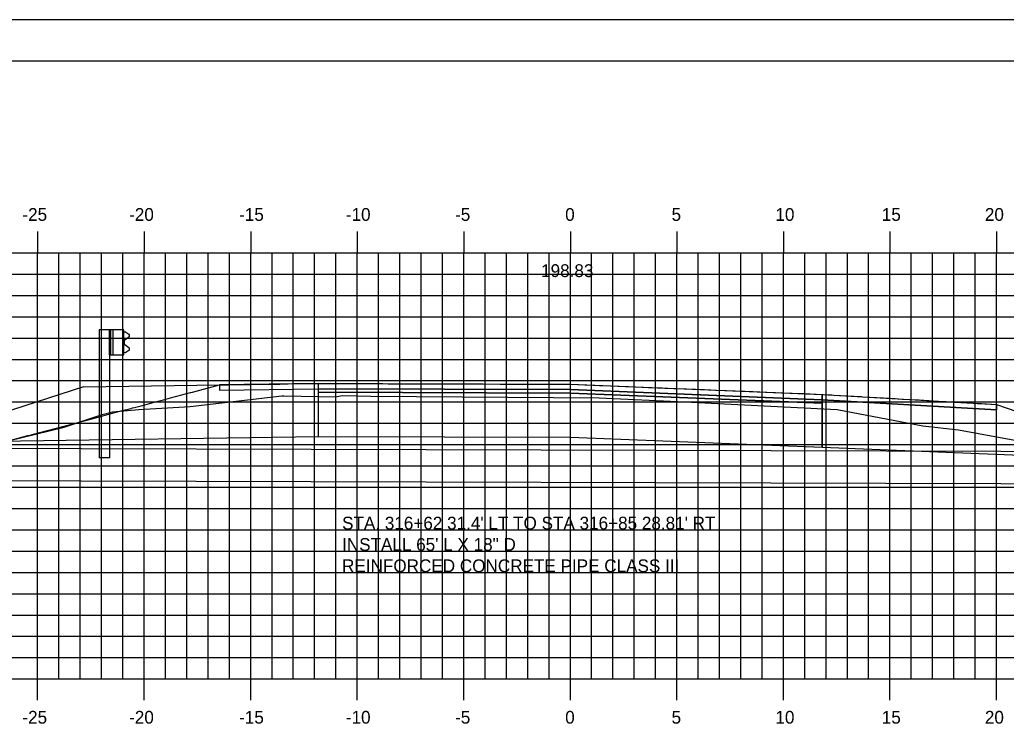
# Model space of a CAD drawing. Extents: x 1138763 to 1138933, y 608981 to 609091.
# Drawn here: x 1138820.35 to 1138866.65, y 609057.92 to 609091.28 of the extents above; entities that cross this region are included whole.
import ezdxf

# ---------------------------------------------------------------- set-up
doc = ezdxf.new("R2010")
doc.units = 0
for name, color, linetype in [('ANNOTATION', 7, 'Continuous'), ('BORDER', 7, 'Continuous'), ('D_Drainage_Culvert', 7, 'Continuous'), ('D_Guardrail_Beam_Lt', 7, 'Continuous'), ('D_Roadway_Centerline', 7, 'Continuous'), ('D_Roadway_Centerline_Text', 7, 'Continuous'), ('D_Roadway_Edge_Shoulder', 7, 'Continuous'), ('D_Roadway_Edge_TW', 7, 'Continuous'), ('D_Roadway_Pavement', 7, 'Continuous'), ('D_Roadway_SubGrade', 7, 'Continuous'), ('H_V ANNOTATION', 7, 'Continuous'), ('MAJOR', 7, 'Continuous'), ('MINOR', 7, 'Continuous'), ('PLOT BOUNDARY', 7, 'Continuous'), ('S_Roadway_Centerline', 7, 'Continuous')]:
    doc.layers.add(name, color=color, linetype=linetype)

msp = doc.modelspace()

# ---------------------------------------------------------------- linework, layer by layer
msp.add_lwpolyline([(1138819.656, 609071.467), (1138820.738, 609071.753), (1138820.904, 609071.797), (1138820.939, 609071.806), (1138822.441, 609072.204), (1138822.794, 609072.298), (1138823.978, 609072.611), (1138824.65, 609072.789), (1138825.12, 609072.913), (1138825.57, 609073.032), (1138825.644, 609073.052), (1138825.734, 609073.076), (1138826.049, 609073.159), (1138826.506, 609073.28), (1138826.704, 609073.333), (1138827.098, 609073.437), (1138827.421, 609073.523), (1138828.362, 609073.772), (1138828.377, 609073.776), (1138828.461, 609073.798), (1138828.628, 609073.842), (1138829.729, 609074.134), (1138829.729, 609074.134), (1138829.73, 609074.134), (1138829.805, 609074.135), (1138829.825, 609074.135), (1138830.183, 609074.141), (1138830.218, 609074.141), (1138830.953, 609074.152), (1138831.189, 609074.156), (1138831.718, 609074.164), (1138832.074, 609074.169), (1138832.299, 609074.173), (1138832.553, 609074.177), (1138832.949, 609074.183), (1138833.753, 609074.195), (1138833.899, 609074.197), (1138833.917, 609074.197), (1138833.929, 609074.198), (1138833.93, 609074.198), (1138834.369, 609074.204), (1138835.187, 609074.202), (1138835.281, 609074.201), (1138835.728, 609074.2), (1138835.786, 609074.2), (1138835.875, 609074.199), (1138836.481, 609074.197), (1138836.511, 609074.197), (1138836.645, 609074.197), (1138837.387, 609074.194), (1138837.642, 609074.193), (1138837.747, 609074.193), (1138838.009, 609074.192), (1138838.855, 609074.189), (1138839.373, 609074.188), (1138839.426, 609074.188), (1138839.498, 609074.187), (1138840.098, 609074.185), (1138840.737, 609074.183), (1138841.007, 609074.182), (1138841.354, 609074.181), (1138841.825, 609074.18), (1138842.1, 609074.179), (1138842.901, 609074.176), (1138843.21, 609074.175), (1138843.273, 609074.175), (1138843.464, 609074.175), (1138844.65, 609074.171), (1138844.828, 609074.17), (1138844.855, 609074.17), (1138845.066, 609074.17), (1138846.192, 609074.166), (1138846.879, 609074.139), (1138846.922, 609074.137), (1138846.963, 609074.135), (1138847.556, 609074.111), (1138847.713, 609074.105), (1138848.778, 609074.062), (1138848.809, 609074.061), (1138848.92, 609074.057), (1138849.861, 609074.019), (1138850.284, 609074.002), (1138850.506, 609073.993), (1138850.634, 609073.988), (1138851.05, 609073.971), (1138851.648, 609073.947), (1138852.066, 609073.93), (1138852.489, 609073.913), (1138852.78, 609073.902), (1138853.012, 609073.892), (1138853.519, 609073.872), (1138854.345, 609073.839), (1138854.355, 609073.839), (1138854.376, 609073.838), (1138854.752, 609073.823), (1138855.739, 609073.783), (1138855.825, 609073.78), (1138856.201, 609073.765), (1138857.028, 609073.732), (1138857.103, 609073.729), (1138857.171, 609073.726), (1138858.015, 609073.692), (1138858.057, 609073.69), (1138858.059, 609073.69), (1138858.467, 609073.666), (1138858.554, 609073.661), (1138859.831, 609073.586), (1138859.849, 609073.585), (1138859.913, 609073.581), (1138860.255, 609073.561), (1138861.195, 609073.506), (1138861.429, 609073.493), (1138861.769, 609073.473), (1138862.162, 609073.45), (1138862.559, 609073.427), (1138863.229, 609073.388), (1138863.625, 609073.364), (1138863.834, 609073.352), (1138863.923, 609073.347), (1138865.098, 609073.279), (1138865.287, 609073.268), (1138865.463, 609073.257), (1138865.481, 609073.256), (1138866.197, 609073.214), (1138866.651, 609073.059)])
at = {"layer": 'BORDER'}
msp.add_lwpolyline([(1138771.192, 608984.335), (1138931.192, 608984.335), (1138931.192, 609089.335), (1138771.192, 609089.335)], close=True, dxfattribs=at)
at = {"layer": 'D_Drainage_Culvert'}
msp.add_lwpolyline([(1138812.433, 609069.671), (1138877.192, 609069.481), (1138877.196, 609070.981), (1138812.438, 609071.171)], close=True, dxfattribs=at)
at = {"layer": 'D_Guardrail_Beam_Lt'}
for p, q in [((1138824.083, 609076.717), (1138824.083, 609070.717)), ((1138824.554, 609076.717), (1138824.083, 609076.717)), ((1138825.241, 609076.717), (1138824.554, 609076.717)), ((1138824.554, 609076.717), (1138824.554, 609075.551)), ((1138824.616, 609076.717), (1138824.616, 609075.551)), ((1138824.72, 609076.717), (1138824.72, 609075.551)), ((1138825.241, 609075.551), (1138825.241, 609076.717)), ((1138825.241, 609076.634), (1138825.315, 609076.619)), ((1138825.331, 609076.613), (1138825.475, 609076.513)), ((1138825.246, 609076.169), (1138825.246, 609076.099)), ((1138825.475, 609076.37), (1138825.279, 609076.234)), ((1138825.279, 609076.035), (1138825.475, 609075.898)), ((1138825.315, 609075.649), (1138825.241, 609075.634)), ((1138825.475, 609075.755), (1138825.331, 609075.655)), ((1138824.554, 609075.551), (1138825.241, 609075.551)), ((1138824.575, 609070.717), (1138824.575, 609075.551)), ((1138824.575, 609070.717), (1138824.083, 609070.717))]:
    msp.add_line(p, q, dxfattribs=at)
for centre, major_axis, start_param, end_param in [((1138825.307, 609076.579), (0.0417, 0), 0.959931, 1.376053), ((1138825.424, 609076.441), (0.0877, 0), 5.323254, 7.243116), ((1138825.325, 609076.169), (-0.0789, 0), 5.323254, 6.283185), ((1138825.325, 609076.099), (-0.0789, 0), 6.283185, 7.243116), ((1138825.307, 609075.689), (0.0417, 0), 4.907132, 5.323254), ((1138825.424, 609075.827), (0.0877, 0), 5.323254, 7.243116)]:
    msp.add_ellipse(centre, major_axis=major_axis, ratio=0.995501, start_param=start_param, end_param=end_param, dxfattribs=at)
at = {"layer": 'D_Roadway_Centerline'}
msp.add_line((1138823.352, 609074.037), (1138829.729, 609074.134), dxfattribs=at)
at = {"layer": 'D_Roadway_Edge_Shoulder'}
for points in [[(1138834.369, 609074.204), (1138829.73, 609074.134), (1138829.73, 609073.884), (1138834.369, 609073.954)], [(1138858.015, 609073.692), (1138866.197, 609073.214), (1138866.197, 609072.964), (1138858.015, 609073.442)]]:
    msp.add_lwpolyline(points, close=True, dxfattribs=at)
at = {"layer": 'D_Roadway_Edge_TW'}
msp.add_lwpolyline([(1138834.369, 609073.954), (1138834.369, 609074.204), (1138846.192, 609074.166), (1138858.015, 609073.692), (1138858.015, 609073.442), (1138846.192, 609073.916)], close=True, dxfattribs=at)
at = {"layer": 'D_Roadway_Pavement'}
msp.add_lwpolyline([(1138834.369, 609073.788), (1138834.369, 609073.954), (1138846.192, 609073.916), (1138858.015, 609073.442), (1138858.015, 609073.276), (1138846.192, 609073.75)], close=True, dxfattribs=at)
at = {"layer": 'D_Roadway_SubGrade'}
msp.add_line((1138834.369, 609071.704), (1138815.942, 609071.425), dxfattribs=at)
msp.add_lwpolyline([(1138823.352, 609074.037), (1138823.352, 609074.037), (1138817.205, 609072.057)], dxfattribs=at)
for points in [[(1138834.369, 609071.704), (1138834.369, 609073.788), (1138846.192, 609073.75), (1138858.015, 609073.276), (1138858.015, 609071.192), (1138846.192, 609071.666)], [(1138858.015, 609073.276), (1138858.015, 609073.442), (1138866.197, 609072.964), (1138866.197, 609073.214), (1138866.197, 609073.214), (1138873.925, 609070.561), (1138858.015, 609071.192)]]:
    msp.add_lwpolyline(points, close=True, dxfattribs=at)
at = {"layer": 'MAJOR'}
for p, q in [((1138821.192, 609081.337), (1138821.192, 609080.335)), ((1138826.192, 609081.337), (1138826.192, 609080.335)), ((1138831.192, 609081.337), (1138831.192, 609080.335)), ((1138836.192, 609081.337), (1138836.192, 609080.335)), ((1138841.192, 609081.337), (1138841.192, 609080.335)), ((1138846.192, 609081.337), (1138846.192, 609080.335)), ((1138851.192, 609081.337), (1138851.192, 609080.335)), ((1138856.192, 609081.337), (1138856.192, 609080.335)), ((1138861.192, 609081.337), (1138861.192, 609080.335)), ((1138866.192, 609081.337), (1138866.192, 609080.335)), ((1138776.192, 609080.335), (1138916.192, 609080.335)), ((1138776.192, 609080.335), (1138916.192, 609080.335)), ((1138821.192, 609060.335), (1138821.192, 609080.335)), ((1138826.192, 609060.335), (1138826.192, 609080.335)), ((1138831.192, 609060.335), (1138831.192, 609080.335)), ((1138836.192, 609060.335), (1138836.192, 609080.335)), ((1138841.192, 609060.335), (1138841.192, 609080.335)), ((1138846.192, 609060.335), (1138846.192, 609080.335)), ((1138851.192, 609060.335), (1138851.192, 609080.335)), ((1138856.192, 609060.335), (1138856.192, 609080.335)), ((1138861.192, 609060.335), (1138861.192, 609080.335)), ((1138866.192, 609060.335), (1138866.192, 609080.335)), ((1138776.192, 609075.335), (1138916.192, 609075.335)), ((1138776.192, 609070.335), (1138916.192, 609070.335)), ((1138776.192, 609065.335), (1138916.192, 609065.335)), ((1138776.192, 609060.335), (1138916.192, 609060.335)), ((1138776.192, 609060.335), (1138916.192, 609060.335)), ((1138821.192, 609059.333), (1138821.192, 609060.335)), ((1138826.192, 609059.333), (1138826.192, 609060.335)), ((1138831.192, 609059.333), (1138831.192, 609060.335)), ((1138836.192, 609059.333), (1138836.192, 609060.335)), ((1138841.192, 609059.333), (1138841.192, 609060.335)), ((1138846.192, 609059.333), (1138846.192, 609060.335)), ((1138851.192, 609059.333), (1138851.192, 609060.335)), ((1138856.192, 609059.333), (1138856.192, 609060.335)), ((1138861.192, 609059.333), (1138861.192, 609060.335)), ((1138866.192, 609059.333), (1138866.192, 609060.335))]:
    msp.add_line(p, q, dxfattribs=at)
at = {"layer": 'MINOR'}
for p, q in [((1138822.192, 609060.335), (1138822.192, 609080.335)), ((1138823.192, 609060.335), (1138823.192, 609080.335)), ((1138824.192, 609060.335), (1138824.192, 609080.335)), ((1138825.192, 609060.335), (1138825.192, 609080.335)), ((1138827.192, 609060.335), (1138827.192, 609080.335)), ((1138828.192, 609060.335), (1138828.192, 609080.335)), ((1138829.192, 609060.335), (1138829.192, 609080.335)), ((1138830.192, 609060.335), (1138830.192, 609080.335)), ((1138832.192, 609060.335), (1138832.192, 609080.335)), ((1138833.192, 609060.335), (1138833.192, 609080.335)), ((1138834.192, 609060.335), (1138834.192, 609080.335)), ((1138835.192, 609060.335), (1138835.192, 609080.335)), ((1138837.192, 609060.335), (1138837.192, 609080.335)), ((1138838.192, 609060.335), (1138838.192, 609080.335)), ((1138839.192, 609060.335), (1138839.192, 609080.335)), ((1138840.192, 609060.335), (1138840.192, 609080.335)), ((1138842.192, 609060.335), (1138842.192, 609080.335)), ((1138843.192, 609060.335), (1138843.192, 609080.335)), ((1138844.192, 609060.335), (1138844.192, 609080.335)), ((1138845.192, 609060.335), (1138845.192, 609080.335)), ((1138847.192, 609060.335), (1138847.192, 609080.335)), ((1138848.192, 609060.335), (1138848.192, 609080.335)), ((1138849.192, 609060.335), (1138849.192, 609080.335)), ((1138850.192, 609060.335), (1138850.192, 609080.335)), ((1138852.192, 609060.335), (1138852.192, 609080.335)), ((1138853.192, 609060.335), (1138853.192, 609080.335)), ((1138854.192, 609060.335), (1138854.192, 609080.335)), ((1138855.192, 609060.335), (1138855.192, 609080.335)), ((1138857.192, 609060.335), (1138857.192, 609080.335)), ((1138858.192, 609060.335), (1138858.192, 609080.335)), ((1138859.192, 609060.335), (1138859.192, 609080.335)), ((1138860.192, 609060.335), (1138860.192, 609080.335)), ((1138862.192, 609060.335), (1138862.192, 609080.335)), ((1138863.192, 609060.335), (1138863.192, 609080.335)), ((1138864.192, 609060.335), (1138864.192, 609080.335)), ((1138865.192, 609060.335), (1138865.192, 609080.335)), ((1138776.192, 609079.335), (1138916.192, 609079.335)), ((1138776.192, 609078.335), (1138916.192, 609078.335)), ((1138776.192, 609077.335), (1138916.192, 609077.335)), ((1138776.192, 609076.335), (1138916.192, 609076.335)), ((1138776.192, 609074.335), (1138916.192, 609074.335)), ((1138776.192, 609073.335), (1138916.192, 609073.335)), ((1138776.192, 609072.335), (1138916.192, 609072.335)), ((1138776.192, 609071.335), (1138916.192, 609071.335)), ((1138776.192, 609069.335), (1138916.192, 609069.335)), ((1138776.192, 609068.335), (1138916.192, 609068.335)), ((1138776.192, 609067.335), (1138916.192, 609067.335)), ((1138776.192, 609066.335), (1138916.192, 609066.335)), ((1138776.192, 609064.335), (1138916.192, 609064.335)), ((1138776.192, 609063.335), (1138916.192, 609063.335)), ((1138776.192, 609062.335), (1138916.192, 609062.335)), ((1138776.192, 609061.335), (1138916.192, 609061.335))]:
    msp.add_line(p, q, dxfattribs=at)
at = {"layer": 'PLOT BOUNDARY'}
msp.add_lwpolyline([(1138763.099, 608981.276), (1138933.099, 608981.276), (1138933.099, 609091.276), (1138763.099, 609091.276)], close=True, dxfattribs=at)
at = {"layer": 'S_Roadway_Centerline'}
msp.add_lwpolyline([(1138816.585, 609070.727), (1138822.444, 609072.146), (1138824.222, 609072.742), (1138824.701, 609072.879), (1138825.945, 609072.976), (1138828.354, 609073.126), (1138832.659, 609073.63), (1138832.748, 609073.618), (1138835.176, 609073.583), (1138835.492, 609073.636), (1138836.837, 609073.613), (1138847.552, 609073.531), (1138851.56, 609073.334), (1138858.717, 609072.973), (1138862.734, 609072.221), (1138864.409, 609072.019), (1138876.86, 609069.741), (1138877.413, 609069.481), (1138878.01, 609069.44), (1138878.412, 609069.518), (1138894.193, 609069.486), (1138916.192, 609069.36)], dxfattribs=at)

# ---------------------------------------------------------------- texts
at = {"layer": 'ANNOTATION'}
for s, p in [("STA. 316+62 31.4' LT TO STA 316+85 28.81' RT", (1138835.48, 609067.348)), ('INSTALL 65\' L X 18" D', (1138835.48, 609066.346)), ('REINFORCED CONCRETE PIPE CLASS III', (1138835.48, 609065.344))]:
    msp.add_text(s, height=0.6, dxfattribs=at).set_placement(p)
at = {"layer": 'D_Roadway_Centerline'}
for s, p in [('C', (1138846.187, 609074.166)), ('L', (1138846.192, 609074.159))]:
    msp.add_text(s, height=0.0146, dxfattribs=at).set_placement(p)
at = {"layer": 'D_Roadway_Centerline_Text'}
msp.add_text('198.83', height=0.6, dxfattribs=at).set_placement((1138844.82, 609079.198))
at = {"layer": 'H_V ANNOTATION'}
for s, p in [('-25', (1138820.478, 609081.835)), ('-20', (1138825.486, 609081.835)), ('-15', (1138830.649, 609081.835)), ('-10', (1138835.657, 609081.835)), ('-5', (1138840.783, 609081.835)), ('0', (1138845.951, 609081.835)), ('5', (1138850.943, 609081.835)), ('10', (1138855.817, 609081.835)), ('15', (1138860.809, 609081.835)), ('20', (1138865.646, 609081.835)), ('-25', (1138820.478, 609058.235)), ('-20', (1138825.486, 609058.235)), ('-15', (1138830.649, 609058.235)), ('-10', (1138835.657, 609058.235)), ('-5', (1138840.783, 609058.235)), ('0', (1138845.951, 609058.235)), ('5', (1138850.943, 609058.235)), ('10', (1138855.817, 609058.235)), ('15', (1138860.809, 609058.235)), ('20', (1138865.646, 609058.235))]:
    msp.add_text(s, height=0.6, dxfattribs=at).set_placement(p)
at = {"layer": 'S_Roadway_Centerline'}
for s, p in [('C', (1138847.547, 609073.531)), ('L', (1138847.552, 609073.523))]:
    msp.add_text(s, height=0.0146, dxfattribs=at).set_placement(p)

doc.saveas('drawing.dxf')
